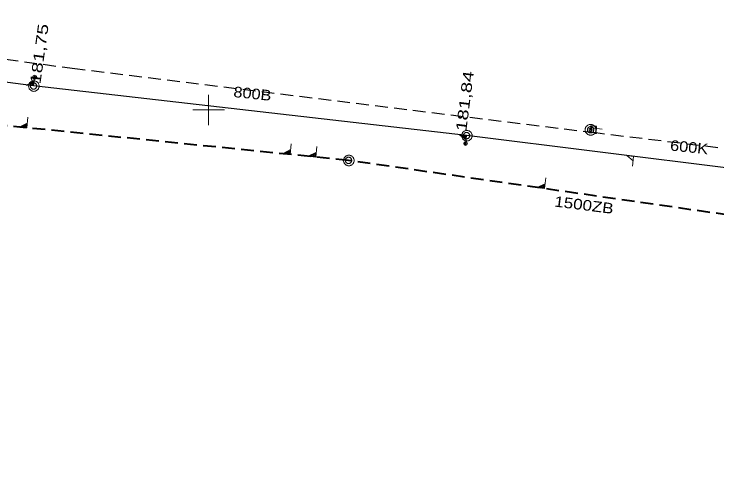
# Model space of a CAD drawing. Extents: x -740851 to -738888, y -1041382 to -1040235.
# Drawn here: x -740018.4 to -739952, y -1040483.7 to -1040440.9 of the extents above; entities that cross this region are included whole.
import ezdxf

# ---------------------------------------------------------------- set-up
doc = ezdxf.new("R2010")
doc.units = 0
doc.header["$LTSCALE"] = 0.4
doc.linetypes.add('MEDIUM_DASHED', pattern=[4.5, 3, -1.5])
for name, color, linetype, lineweight in [('1', 7, 'Continuous', 13), ('18', 7, 'Continuous', 13), ('8', 7, 'Continuous', 13)]:
    doc.layers.add(name, color=color, linetype=linetype, lineweight=lineweight)

msp = doc.modelspace()

# ---------------------------------------------------------------- linework, layer by layer
at = {"layer": '1'}
for p, q in [((-740000, -1040448.571), (-740000, -1040451.429)), ((-740001.48, -1040450), (-739998.48, -1040450))]:
    msp.add_line(p, q, dxfattribs=at)
at = {"layer": '18', "lineweight": 25}
for p, q in [((-740016.53, -1040447.73), (-740055.32, -1040442.7)), ((-739975.63, -1040452.42), (-740016.53, -1040447.73)), ((-739935.25, -1040457.45), (-739975.63, -1040452.42))]:
    msp.add_line(p, q, dxfattribs=at)
at = {"layer": '18', "linetype": 'MEDIUM_DASHED', "lineweight": 40}
for p, q in [((-739986.78, -1040454.76), (-740046.72, -1040448.69)), ((-739934.84, -1040462.24), (-739986.78, -1040454.76))]:
    msp.add_line(p, q, dxfattribs=at)
at = {"layer": '18'}
for points in [[(-740016.413, -1040446.73), (-740016.527, -1040447.728), (-740017.239, -1040447.646), (-740016.476, -1040447.278)], [(-740016.54, -1040447.372), (-740016.573, -1040447.662), (-740017.028, -1040447.61), (-740016.535, -1040447.372)], [(-740016.604, -1040447.471), (-740016.621, -1040447.616), (-740016.854, -1040447.589), (-740016.599, -1040447.471)], [(-740017.072, -1040450.68), (-740017.173, -1040451.68), (-740017.887, -1040451.608), (-740017.128, -1040451.229)], [(-740017.19, -1040451.324), (-740017.22, -1040451.615), (-740017.676, -1040451.569), (-740017.185, -1040451.324)], [(-740017.253, -1040451.423), (-740017.268, -1040451.569), (-740017.502, -1040451.545), (-740017.249, -1040451.424)], [(-739975.744, -1040453.334), (-739975.63, -1040452.42), (-739976.283, -1040452.339), (-739975.681, -1040452.832)], [(-739975.718, -1040452.735), (-739975.685, -1040452.469), (-739976.102, -1040452.417), (-739975.714, -1040452.735)], [(-739975.754, -1040452.633), (-739975.737, -1040452.5), (-739975.951, -1040452.473), (-739975.75, -1040452.633)], [(-739992.199, -1040453.199), (-739992.3, -1040454.199), (-739993.014, -1040454.126), (-739992.255, -1040453.747)], [(-739989.762, -1040453.445), (-739989.863, -1040454.445), (-739990.577, -1040454.373), (-739989.817, -1040453.994)], [(-739992.317, -1040453.842), (-739992.347, -1040454.134), (-739992.803, -1040454.087), (-739992.313, -1040453.843)], [(-739992.381, -1040453.942), (-739992.395, -1040454.088), (-739992.629, -1040454.064), (-739992.376, -1040453.943)], [(-739989.88, -1040454.089), (-739989.909, -1040454.38), (-739990.365, -1040454.334), (-739989.875, -1040454.09)], [(-739989.943, -1040454.189), (-739989.958, -1040454.334), (-739990.192, -1040454.311), (-739989.938, -1040454.189)], [(-739959.966, -1040455.304), (-739959.851, -1040454.385), (-739960.506, -1040454.304), (-739959.903, -1040454.8)], [(-739968.129, -1040456.423), (-739968.273, -1040457.423), (-739968.987, -1040457.32), (-739968.208, -1040456.972)], [(-739968.275, -1040457.064), (-739968.317, -1040457.356), (-739968.773, -1040457.29), (-739968.27, -1040457.065)], [(-739968.343, -1040457.162), (-739968.364, -1040457.307), (-739968.597, -1040457.274), (-739968.338, -1040457.163)]]:
    msp.add_lwpolyline(points, dxfattribs=at)
for points in [[(-740016, -1040447.74), (-740016.01, -1040447.69), (-740016.01, -1040447.64), (-740016.03, -1040447.59), (-740016.05, -1040447.54), (-740016.07, -1040447.49), (-740016.1, -1040447.45), (-740016.13, -1040447.41), (-740016.17, -1040447.37), (-740016.21, -1040447.34), (-740016.25, -1040447.31), (-740016.3, -1040447.29), (-740016.35, -1040447.27), (-740016.4, -1040447.25), (-740016.45, -1040447.25), (-740016.5, -1040447.24), (-740016.55, -1040447.25), (-740016.6, -1040447.25), (-740016.65, -1040447.27), (-740016.7, -1040447.29), (-740016.75, -1040447.31), (-740016.79, -1040447.34), (-740016.83, -1040447.37), (-740016.87, -1040447.41), (-740016.9, -1040447.45), (-740016.93, -1040447.49), (-740016.95, -1040447.54), (-740016.97, -1040447.59), (-740016.99, -1040447.64), (-740016.99, -1040447.69), (-740017, -1040447.74), (-740016.99, -1040447.79), (-740016.99, -1040447.84), (-740016.97, -1040447.89), (-740016.95, -1040447.94), (-740016.93, -1040447.99), (-740016.9, -1040448.03), (-740016.87, -1040448.07), (-740016.83, -1040448.11), (-740016.79, -1040448.14), (-740016.75, -1040448.17), (-740016.7, -1040448.19), (-740016.65, -1040448.21), (-740016.6, -1040448.23), (-740016.55, -1040448.23), (-740016.5, -1040448.24), (-740016.45, -1040448.23), (-740016.4, -1040448.23), (-740016.35, -1040448.21), (-740016.3, -1040448.19), (-740016.25, -1040448.17), (-740016.21, -1040448.14), (-740016.17, -1040448.11), (-740016.13, -1040448.07), (-740016.1, -1040448.03), (-740016.07, -1040447.99), (-740016.05, -1040447.94), (-740016.03, -1040447.89), (-740016.01, -1040447.84), (-740016.01, -1040447.79)], [(-740016.23, -1040447.73), (-740016.23, -1040447.7), (-740016.236, -1040447.67), (-740016.242, -1040447.64), (-740016.254, -1040447.61), (-740016.272, -1040447.58), (-740016.29, -1040447.556), (-740016.308, -1040447.532), (-740016.332, -1040447.508), (-740016.356, -1040447.49), (-740016.38, -1040447.472), (-740016.41, -1040447.454), (-740016.44, -1040447.442), (-740016.47, -1040447.436), (-740016.5, -1040447.43), (-740016.53, -1040447.43), (-740016.56, -1040447.43), (-740016.59, -1040447.436), (-740016.62, -1040447.442), (-740016.65, -1040447.454), (-740016.68, -1040447.472), (-740016.704, -1040447.49), (-740016.728, -1040447.508), (-740016.752, -1040447.532), (-740016.77, -1040447.556), (-740016.788, -1040447.58), (-740016.806, -1040447.61), (-740016.818, -1040447.64), (-740016.824, -1040447.67), (-740016.83, -1040447.7), (-740016.83, -1040447.73), (-740016.83, -1040447.76), (-740016.824, -1040447.79), (-740016.818, -1040447.82), (-740016.806, -1040447.85), (-740016.788, -1040447.88), (-740016.77, -1040447.904), (-740016.752, -1040447.928), (-740016.728, -1040447.952), (-740016.704, -1040447.97), (-740016.68, -1040447.988), (-740016.65, -1040448.006), (-740016.62, -1040448.018), (-740016.59, -1040448.024), (-740016.56, -1040448.03), (-740016.53, -1040448.03), (-740016.5, -1040448.03), (-740016.47, -1040448.024), (-740016.44, -1040448.018), (-740016.41, -1040448.006), (-740016.38, -1040447.988), (-740016.356, -1040447.97), (-740016.332, -1040447.952), (-740016.308, -1040447.928), (-740016.29, -1040447.904), (-740016.272, -1040447.88), (-740016.254, -1040447.85), (-740016.242, -1040447.82), (-740016.236, -1040447.79), (-740016.23, -1040447.76)], [(-739975.1, -1040452.43), (-739975.11, -1040452.38), (-739975.11, -1040452.33), (-739975.13, -1040452.28), (-739975.15, -1040452.23), (-739975.17, -1040452.18), (-739975.2, -1040452.14), (-739975.23, -1040452.1), (-739975.27, -1040452.06), (-739975.31, -1040452.03), (-739975.35, -1040452), (-739975.4, -1040451.98), (-739975.45, -1040451.96), (-739975.5, -1040451.94), (-739975.55, -1040451.94), (-739975.6, -1040451.93), (-739975.65, -1040451.94), (-739975.7, -1040451.94), (-739975.75, -1040451.96), (-739975.8, -1040451.98), (-739975.85, -1040452), (-739975.89, -1040452.03), (-739975.93, -1040452.06), (-739975.97, -1040452.1), (-739976, -1040452.14), (-739976.03, -1040452.18), (-739976.05, -1040452.23), (-739976.07, -1040452.28), (-739976.09, -1040452.33), (-739976.09, -1040452.38), (-739976.1, -1040452.43), (-739976.09, -1040452.48), (-739976.09, -1040452.53), (-739976.07, -1040452.58), (-739976.05, -1040452.63), (-739976.03, -1040452.68), (-739976, -1040452.72), (-739975.97, -1040452.76), (-739975.93, -1040452.8), (-739975.89, -1040452.83), (-739975.85, -1040452.86), (-739975.8, -1040452.88), (-739975.75, -1040452.9), (-739975.7, -1040452.92), (-739975.65, -1040452.92), (-739975.6, -1040452.93), (-739975.55, -1040452.92), (-739975.5, -1040452.92), (-739975.45, -1040452.9), (-739975.4, -1040452.88), (-739975.35, -1040452.86), (-739975.31, -1040452.83), (-739975.27, -1040452.8), (-739975.23, -1040452.76), (-739975.2, -1040452.72), (-739975.17, -1040452.68), (-739975.15, -1040452.63), (-739975.13, -1040452.58), (-739975.11, -1040452.53), (-739975.11, -1040452.48)], [(-739975.33, -1040452.42), (-739975.33, -1040452.39), (-739975.336, -1040452.36), (-739975.342, -1040452.33), (-739975.354, -1040452.3), (-739975.372, -1040452.27), (-739975.39, -1040452.246), (-739975.408, -1040452.222), (-739975.432, -1040452.198), (-739975.456, -1040452.18), (-739975.48, -1040452.162), (-739975.51, -1040452.144), (-739975.54, -1040452.132), (-739975.57, -1040452.126), (-739975.6, -1040452.12), (-739975.63, -1040452.12), (-739975.66, -1040452.12), (-739975.69, -1040452.126), (-739975.72, -1040452.132), (-739975.75, -1040452.144), (-739975.78, -1040452.162), (-739975.804, -1040452.18), (-739975.828, -1040452.198), (-739975.852, -1040452.222), (-739975.87, -1040452.246), (-739975.888, -1040452.27), (-739975.906, -1040452.3), (-739975.918, -1040452.33), (-739975.924, -1040452.36), (-739975.93, -1040452.39), (-739975.93, -1040452.42), (-739975.93, -1040452.45), (-739975.924, -1040452.48), (-739975.918, -1040452.51), (-739975.906, -1040452.54), (-739975.888, -1040452.57), (-739975.87, -1040452.594), (-739975.852, -1040452.618), (-739975.828, -1040452.642), (-739975.804, -1040452.66), (-739975.78, -1040452.678), (-739975.75, -1040452.696), (-739975.72, -1040452.708), (-739975.69, -1040452.714), (-739975.66, -1040452.72), (-739975.63, -1040452.72), (-739975.6, -1040452.72), (-739975.57, -1040452.714), (-739975.54, -1040452.708), (-739975.51, -1040452.696), (-739975.48, -1040452.678), (-739975.456, -1040452.66), (-739975.432, -1040452.642), (-739975.408, -1040452.618), (-739975.39, -1040452.594), (-739975.372, -1040452.57), (-739975.354, -1040452.54), (-739975.342, -1040452.51), (-739975.336, -1040452.48), (-739975.33, -1040452.45)], [(-739986.25, -1040454.77), (-739986.26, -1040454.72), (-739986.26, -1040454.67), (-739986.28, -1040454.62), (-739986.3, -1040454.57), (-739986.32, -1040454.52), (-739986.35, -1040454.48), (-739986.38, -1040454.44), (-739986.42, -1040454.4), (-739986.46, -1040454.37), (-739986.5, -1040454.34), (-739986.55, -1040454.32), (-739986.6, -1040454.3), (-739986.65, -1040454.28), (-739986.7, -1040454.28), (-739986.75, -1040454.27), (-739986.8, -1040454.28), (-739986.85, -1040454.28), (-739986.9, -1040454.3), (-739986.95, -1040454.32), (-739987, -1040454.34), (-739987.04, -1040454.37), (-739987.08, -1040454.4), (-739987.12, -1040454.44), (-739987.15, -1040454.48), (-739987.18, -1040454.52), (-739987.2, -1040454.57), (-739987.22, -1040454.62), (-739987.24, -1040454.67), (-739987.24, -1040454.72), (-739987.25, -1040454.77), (-739987.24, -1040454.82), (-739987.24, -1040454.87), (-739987.22, -1040454.92), (-739987.2, -1040454.97), (-739987.18, -1040455.02), (-739987.15, -1040455.06), (-739987.12, -1040455.1), (-739987.08, -1040455.14), (-739987.04, -1040455.17), (-739987, -1040455.2), (-739986.95, -1040455.22), (-739986.9, -1040455.24), (-739986.85, -1040455.26), (-739986.8, -1040455.26), (-739986.75, -1040455.27), (-739986.7, -1040455.26), (-739986.65, -1040455.26), (-739986.6, -1040455.24), (-739986.55, -1040455.22), (-739986.5, -1040455.2), (-739986.46, -1040455.17), (-739986.42, -1040455.14), (-739986.38, -1040455.1), (-739986.35, -1040455.06), (-739986.32, -1040455.02), (-739986.3, -1040454.97), (-739986.28, -1040454.92), (-739986.26, -1040454.87), (-739986.26, -1040454.82)], [(-739986.48, -1040454.76), (-739986.48, -1040454.73), (-739986.486, -1040454.7), (-739986.492, -1040454.67), (-739986.504, -1040454.64), (-739986.522, -1040454.61), (-739986.54, -1040454.586), (-739986.558, -1040454.562), (-739986.582, -1040454.538), (-739986.606, -1040454.52), (-739986.63, -1040454.502), (-739986.66, -1040454.484), (-739986.69, -1040454.472), (-739986.72, -1040454.466), (-739986.75, -1040454.46), (-739986.78, -1040454.46), (-739986.81, -1040454.46), (-739986.84, -1040454.466), (-739986.87, -1040454.472), (-739986.9, -1040454.484), (-739986.93, -1040454.502), (-739986.954, -1040454.52), (-739986.978, -1040454.538), (-739987.002, -1040454.562), (-739987.02, -1040454.586), (-739987.038, -1040454.61), (-739987.056, -1040454.64), (-739987.068, -1040454.67), (-739987.074, -1040454.7), (-739987.08, -1040454.73), (-739987.08, -1040454.76), (-739987.08, -1040454.79), (-739987.074, -1040454.82), (-739987.068, -1040454.85), (-739987.056, -1040454.88), (-739987.038, -1040454.91), (-739987.02, -1040454.934), (-739987.002, -1040454.958), (-739986.978, -1040454.982), (-739986.954, -1040455), (-739986.93, -1040455.018), (-739986.9, -1040455.036), (-739986.87, -1040455.048), (-739986.84, -1040455.054), (-739986.81, -1040455.06), (-739986.78, -1040455.06), (-739986.75, -1040455.06), (-739986.72, -1040455.054), (-739986.69, -1040455.048), (-739986.66, -1040455.036), (-739986.63, -1040455.018), (-739986.606, -1040455), (-739986.582, -1040454.982), (-739986.558, -1040454.958), (-739986.54, -1040454.934), (-739986.522, -1040454.91), (-739986.504, -1040454.88), (-739986.492, -1040454.85), (-739986.486, -1040454.82), (-739986.48, -1040454.79)]]:
    msp.add_lwpolyline(points, close=True, dxfattribs=at)
for centre, radius in [((-740016.435, -1040446.914), 0.189), ((-740016.435, -1040446.912), 0.0935), ((-739975.723, -1040453.168), 0.174), ((-739975.724, -1040453.169), 0.0858)]:
    msp.add_circle(centre, radius, dxfattribs=at)
at = {"layer": '8'}
for p, q in [((-739962.83, -1040451.816), (-739963.83, -1040451.695)), ((-739963.47, -1040452.222), (-739963.37, -1040452.122)), ((-739963.47, -1040452.122), (-739963.37, -1040452.222)), ((-739963.47, -1040452.122), (-739963.47, -1040452.142)), ((-739963.47, -1040452.122), (-739963.45, -1040452.122)), ((-739963.47, -1040452.222), (-739963.47, -1040452.202)), ((-739963.47, -1040452.222), (-739963.45, -1040452.222)), ((-739963.37, -1040452.122), (-739963.39, -1040452.122)), ((-739963.37, -1040452.222), (-739963.39, -1040452.222)), ((-739963.37, -1040452.122), (-739963.37, -1040452.142)), ((-739963.37, -1040452.222), (-739963.37, -1040452.202))]:
    msp.add_line(p, q, dxfattribs=at)
at = {"layer": '8', "lineweight": 25}
msp.add_line((-739963.421, -1040452.173), (-739963.37, -1040451.75), dxfattribs=at)
at = {"layer": '8', "linetype": 'MEDIUM_DASHED', "lineweight": 25}
for points in [[(-739963.421, -1040452.173), (-740012.64, -1040446.12), (-740051.09, -1040440.94)], [(-739809.48, -1040483.712), (-739832.13, -1040476.03), (-739840.77, -1040473.27), (-739864.43, -1040466.88), (-739898.28, -1040460.1), (-739963.421, -1040452.173)]]:
    msp.add_lwpolyline(points, dxfattribs=at)
at = {"layer": '8'}
for points in [[(-739963.415, -1040451.87), (-739963.415, -1040451.824), (-739963.415, -1040451.764), (-739963.43, -1040451.718), (-739963.445, -1040451.657), (-739963.475, -1040451.612), (-739963.506, -1040451.567), (-739963.536, -1040451.536), (-739963.581, -1040451.491), (-739963.612, -1040451.461), (-739963.657, -1040451.43), (-739963.703, -1040451.4), (-739963.763, -1040451.385), (-739963.809, -1040451.37), (-739963.869, -1040451.37), (-739963.915, -1040451.37), (-739963.975, -1040451.37), (-739964.021, -1040451.37), (-739964.066, -1040451.385), (-739964.127, -1040451.4), (-739964.172, -1040451.43), (-739964.218, -1040451.461), (-739964.248, -1040451.491), (-739964.293, -1040451.536), (-739964.324, -1040451.567), (-739964.354, -1040451.612), (-739964.384, -1040451.657), (-739964.399, -1040451.718), (-739964.415, -1040451.764), (-739964.415, -1040451.824), (-739964.415, -1040451.87), (-739964.415, -1040451.93), (-739964.415, -1040451.976), (-739964.399, -1040452.021), (-739964.384, -1040452.082), (-739964.354, -1040452.127), (-739964.324, -1040452.173), (-739964.293, -1040452.203), (-739964.248, -1040452.248), (-739964.218, -1040452.279), (-739964.172, -1040452.309), (-739964.127, -1040452.339), (-739964.066, -1040452.354), (-739964.021, -1040452.37), (-739963.975, -1040452.37), (-739963.915, -1040452.37), (-739963.869, -1040452.37), (-739963.809, -1040452.37), (-739963.763, -1040452.354), (-739963.703, -1040452.339), (-739963.657, -1040452.309), (-739963.612, -1040452.279), (-739963.581, -1040452.248), (-739963.536, -1040452.203), (-739963.506, -1040452.173), (-739963.475, -1040452.127), (-739963.445, -1040452.082), (-739963.43, -1040452.021), (-739963.415, -1040451.976), (-739963.415, -1040451.93)], [(-739963.612, -1040451.87), (-739963.612, -1040451.839), (-739963.627, -1040451.809), (-739963.627, -1040451.779), (-739963.642, -1040451.748), (-739963.657, -1040451.718), (-739963.672, -1040451.688), (-739963.687, -1040451.673), (-739963.718, -1040451.642), (-739963.733, -1040451.627), (-739963.763, -1040451.612), (-739963.793, -1040451.597), (-739963.824, -1040451.582), (-739963.854, -1040451.582), (-739963.884, -1040451.567), (-739963.915, -1040451.567), (-739963.945, -1040451.567), (-739963.975, -1040451.582), (-739964.006, -1040451.582), (-739964.036, -1040451.597), (-739964.066, -1040451.612), (-739964.096, -1040451.627), (-739964.112, -1040451.642), (-739964.142, -1040451.673), (-739964.157, -1040451.688), (-739964.172, -1040451.718), (-739964.187, -1040451.748), (-739964.203, -1040451.779), (-739964.203, -1040451.809), (-739964.218, -1040451.839), (-739964.218, -1040451.87), (-739964.218, -1040451.9), (-739964.203, -1040451.93), (-739964.203, -1040451.961), (-739964.187, -1040451.991), (-739964.172, -1040452.021), (-739964.157, -1040452.051), (-739964.142, -1040452.067), (-739964.112, -1040452.097), (-739964.096, -1040452.112), (-739964.066, -1040452.127), (-739964.036, -1040452.142), (-739964.006, -1040452.157), (-739963.975, -1040452.157), (-739963.945, -1040452.173), (-739963.915, -1040452.173), (-739963.884, -1040452.173), (-739963.854, -1040452.157), (-739963.824, -1040452.157), (-739963.793, -1040452.142), (-739963.763, -1040452.127), (-739963.733, -1040452.112), (-739963.718, -1040452.097), (-739963.687, -1040452.067), (-739963.672, -1040452.051), (-739963.657, -1040452.021), (-739963.642, -1040451.991), (-739963.627, -1040451.961), (-739963.627, -1040451.93), (-739963.612, -1040451.9)], [(-739963.778, -1040451.87), (-739963.778, -1040451.854), (-739963.793, -1040451.839), (-739963.793, -1040451.824), (-739963.793, -1040451.809), (-739963.809, -1040451.809), (-739963.809, -1040451.794), (-739963.824, -1040451.779), (-739963.839, -1040451.764), (-739963.854, -1040451.764), (-739963.854, -1040451.748), (-739963.869, -1040451.748), (-739963.884, -1040451.748), (-739963.899, -1040451.733), (-739963.915, -1040451.733), (-739963.93, -1040451.733), (-739963.945, -1040451.748), (-739963.96, -1040451.748), (-739963.975, -1040451.748), (-739963.975, -1040451.764), (-739963.99, -1040451.764), (-739964.006, -1040451.779), (-739964.021, -1040451.794), (-739964.036, -1040451.809), (-739964.036, -1040451.824), (-739964.036, -1040451.839), (-739964.051, -1040451.854), (-739964.051, -1040451.87), (-739964.051, -1040451.885), (-739964.036, -1040451.9), (-739964.036, -1040451.915), (-739964.036, -1040451.93), (-739964.021, -1040451.945), (-739964.006, -1040451.961), (-739963.99, -1040451.976), (-739963.975, -1040451.991), (-739963.96, -1040451.991), (-739963.945, -1040451.991), (-739963.93, -1040452.006), (-739963.915, -1040452.006), (-739963.899, -1040452.006), (-739963.884, -1040451.991), (-739963.869, -1040451.991), (-739963.854, -1040451.991), (-739963.839, -1040451.976), (-739963.824, -1040451.961), (-739963.809, -1040451.945), (-739963.809, -1040451.93), (-739963.793, -1040451.93), (-739963.793, -1040451.915), (-739963.793, -1040451.9), (-739963.778, -1040451.885)], [(-739963.37, -1040452.172), (-739963.37, -1040452.167), (-739963.371, -1040452.162), (-739963.372, -1040452.157), (-739963.374, -1040452.152), (-739963.377, -1040452.147), (-739963.38, -1040452.143), (-739963.383, -1040452.139), (-739963.387, -1040452.135), (-739963.391, -1040452.132), (-739963.395, -1040452.129), (-739963.4, -1040452.126), (-739963.405, -1040452.124), (-739963.41, -1040452.123), (-739963.415, -1040452.122), (-739963.42, -1040452.122), (-739963.425, -1040452.122), (-739963.43, -1040452.123), (-739963.435, -1040452.124), (-739963.44, -1040452.126), (-739963.445, -1040452.129), (-739963.449, -1040452.132), (-739963.453, -1040452.135), (-739963.457, -1040452.139), (-739963.46, -1040452.143), (-739963.463, -1040452.147), (-739963.466, -1040452.152), (-739963.468, -1040452.157), (-739963.469, -1040452.162), (-739963.47, -1040452.167), (-739963.47, -1040452.172), (-739963.47, -1040452.177), (-739963.469, -1040452.182), (-739963.468, -1040452.187), (-739963.466, -1040452.192), (-739963.463, -1040452.197), (-739963.46, -1040452.201), (-739963.457, -1040452.205), (-739963.453, -1040452.209), (-739963.449, -1040452.212), (-739963.445, -1040452.215), (-739963.44, -1040452.218), (-739963.435, -1040452.22), (-739963.43, -1040452.221), (-739963.425, -1040452.222), (-739963.42, -1040452.222), (-739963.415, -1040452.222), (-739963.41, -1040452.221), (-739963.405, -1040452.22), (-739963.4, -1040452.218), (-739963.395, -1040452.215), (-739963.391, -1040452.212), (-739963.387, -1040452.209), (-739963.383, -1040452.205), (-739963.38, -1040452.201), (-739963.377, -1040452.197), (-739963.374, -1040452.192), (-739963.372, -1040452.187), (-739963.371, -1040452.182), (-739963.37, -1040452.177)]]:
    msp.add_lwpolyline(points, close=True, dxfattribs=at)
at = {"layer": '8', "lineweight": 25}
msp.add_lwpolyline([(-739963.37, -1040451.75), (-739963.347, -1040451.552), (-739963.901, -1040451.484), (-739963.93, -1040451.9)], dxfattribs=at)

# ---------------------------------------------------------------- texts
at = {"layer": '18'}
for s, rotation, width, p in [('181,75', 82.032, 1.4, (-740015.889, -1040447.606)), ('181,84', 82.738, 1.4, (-739975.661, -1040452.06)), ('800B', 354.027, 1.15, (-739997.688, -1040448.766)), ('600K', 354.174, 1.15, (-739956.443, -1040453.822)), ('1500ZB', 352.805, 1.2, (-739967.387, -1040459.112))]:
    msp.add_text(s, height=1, rotation=rotation, dxfattribs=dict(at, width=width)).set_placement(p)

doc.saveas('drawing.dxf')
